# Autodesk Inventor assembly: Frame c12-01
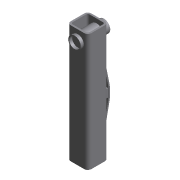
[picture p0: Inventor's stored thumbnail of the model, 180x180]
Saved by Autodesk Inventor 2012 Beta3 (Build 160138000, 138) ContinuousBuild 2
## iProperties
Created: 2011-01
Part Number: Frame c12-01
Document SubType Name: Assembly
Designer: Beta-8540w
_FrameDoc: Frame Assembly
_Version: 15.0.0
Author: Beta-8540w
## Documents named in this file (10)
- C:\Inventor 2012 Essentials\Assemblies\Chapter 12\Frame\Frame c12-01.iam
- C:\Inventor 2012 Essentials\Assemblies\Chapter 12\Frame\Skeleton c12-01.ipt
- C:\Inventor 2012 Essentials\Assemblies\Chapter 12\Frame\ISO 70x70x6 00000001.ipt
- ISO 70x70x6 00000001.ipt
- C:\Inventor 2012 Essentials\Assemblies\Chapter 12\Frame\ISO 30x 5 00000002.ipt
- ISO 30x 5 00000002.ipt
- C:\Inventor 2012 Essentials\Assemblies\Chapter 12\Frame\ISO 28x 28_ 00000003.ipt
- ISO 28x 28_ 00000003.ipt
- C:\Inventor 2012 Essentials\Assemblies\Chapter 12\Frame\ISO 33.7x2.5 00000005.ipt
- ISO 42.4x3.0 00000004.ipt
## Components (5 placed, 5 different names)
1. Frame Reference Model
2. ISO 70x70x6 00000001:1
3. ISO 30x 5 00000002:1
4. ISO 28x 28_ 00000003:1
5. ISO 33.7x2.5 00000005:1
